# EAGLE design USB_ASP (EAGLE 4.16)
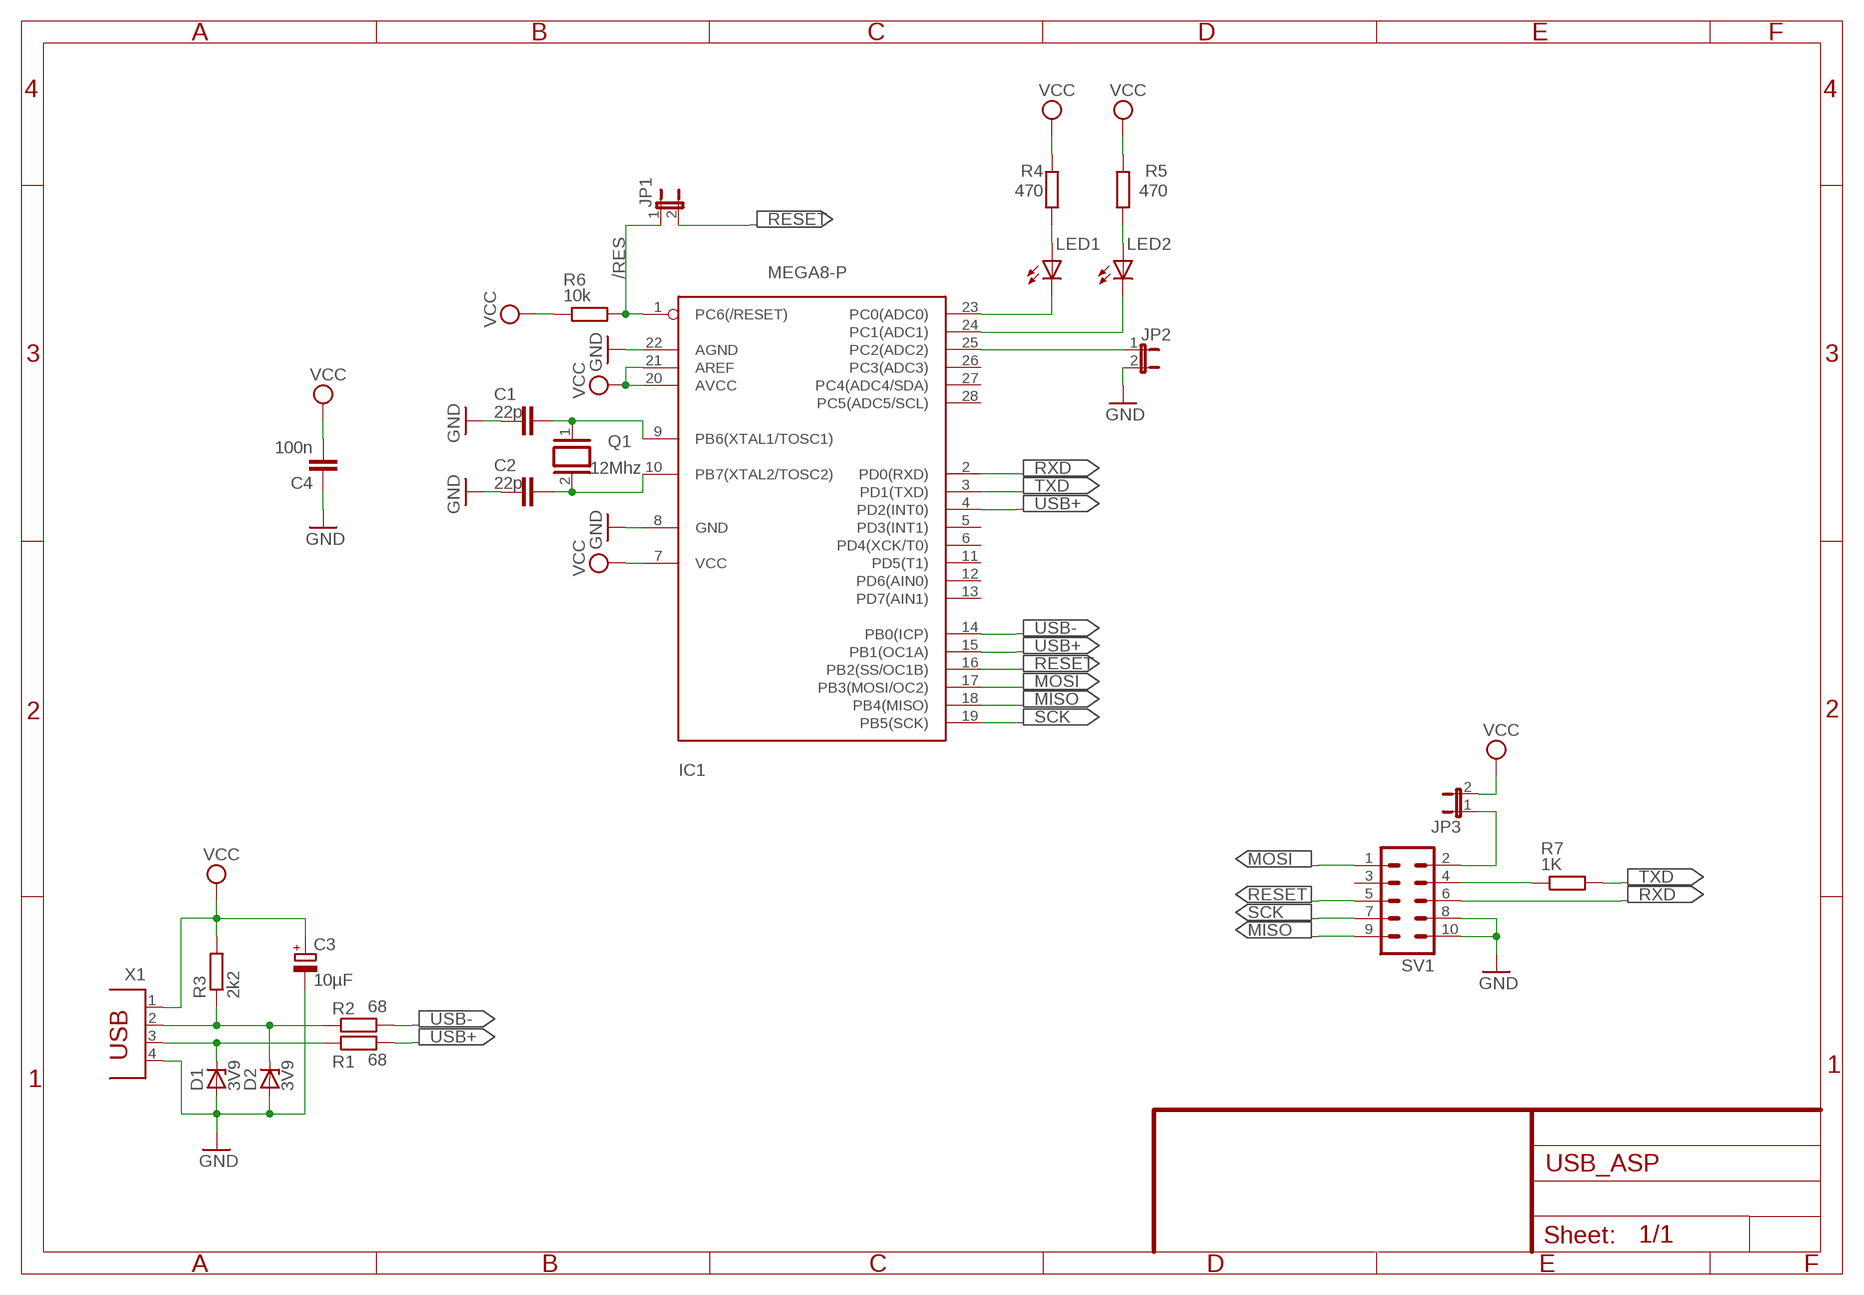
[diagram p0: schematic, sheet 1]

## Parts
C1  22p  C-EU025-024X044  [C025-024X044]
C2  22p  C-EU025-024X044  [C025-024X044]
C3  10µF  CPOL-EUE2.5-6  [E2,5-6]
C4  100n  C-EU025-024X044  [C025-024X044]
D1  3V9  BZX55  [DO35Z10]
D2  3V9  BZX55  [DO35Z10]
IC1  MEGA8-P  [DIL28-3]
JP1  JP1E  [JP1]
JP2  JP1E  [JP1]
JP3  JP1E  [JP1]
LED1  LED3MM  [LED3MM]
LED2  LED3MM  [LED3MM]
Q1  12Mhz  XTAL/S  [QS]
R1  68  R-EU_0207/10  [0207/10]
R2  68  R-EU_0207/10  [0207/10]
R3  2k2  R-EU_0207/10  [0207/10]
R4  470  R-EU_0207/10  [0207/10]
R5  470  R-EU_0207/10  [0207/10]
R6  10k  R-EU_0207/10  [0207/10]
R7  1K  R-EU_0207/10  [0207/10]
SV1  ML10L  [ML10L]
X1  PN61729  [PN61729]

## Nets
/RES: IC1.1(PC6(/RESET)) JP1.1 R6.2
GND: C1.1 C2.1 C3.- C4.1 D1.A D2.A IC1.8(GND) IC1.22(AGND) JP2.2 SV1.8 SV1.10 X1.4
MISO: IC1.18(PB4(MISO)) SV1.9
MOSI: IC1.17(PB3(MOSI/OC2)) SV1.1
N$3: C1.2 IC1.9(PB6(XTAL1/TOSC1)) Q1.1
N$4: C2.2 IC1.10(PB7(XTAL2/TOSC2)) Q1.2
N$5: D1.C R1.1 X1.3
N$6: D2.C R2.1 R3.1 X1.2
N$7: LED1.A R4.1
N$8: LED2.A R5.1
N$9: IC1.23(PC0(ADC0)) LED1.K(C)
N$10: IC1.24(PC1(ADC1)) LED2.K(C)
N$11: IC1.25(PC2(ADC2)) JP2.1
N$12: JP3.1 SV1.2
N$13: R7.1 SV1.4
RESET: IC1.16(PB2(SS/OC1B)) JP1.2 SV1.5
RXD: IC1.2(PD0(RXD)) SV1.6
SCK: IC1.19(PB5(SCK)) SV1.7
TXD: IC1.3(PD1(TXD)) R7.2
USB+: IC1.4(PD2(INT0)) IC1.15(PB1(OC1A)) R1.2
USB-: IC1.14(PB0(ICP)) R2.2
VCC: C3.+ C4.2 IC1.7(VCC) IC1.20(AVCC) IC1.21(AREF) JP3.2 R3.2 R4.2 R5.2 R6.1 X1.1
Unconnected: IC1.5(PD3(INT1)) IC1.6(PD4(XCK/T0)) IC1.11(PD5(T1)) IC1.12(PD6(AIN0)) IC1.13(PD7(AIN1)) IC1.26(PC3(ADC3)) IC1.27(PC4(ADC4/SDA)) IC1.28(PC5(ADC5/SCL)) SV1.3

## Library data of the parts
C1 C2 C4 = rcl:C-EU: CAPACITOR, European symbol
C3 = rcl:CPOL-EU: POLARIZED CAPACITOR, European symbol
D1 D2 = diode:BZX55: Z DIODE
IC1 = avr-1:MEGA8-P: MICROCONTROLLER 8 Kbytes FLASH 1 kbytes SRAM 512 bytes EEPROM USART 4-channel 10 bit ADC 2-channel 8 bit ADC
JP1-JP3 = jumper:JP1E: JUMPER
LED1 LED2 = led:LED: LED
Q1 = special:XTAL/S: CRYSTAL
R1-R7 = rcl:R-EU_: RESISTOR, European symbol
SV1 = con-harting-ml:ML10: HARTING
X1 = con-berg:PN61729: BERG USB connector

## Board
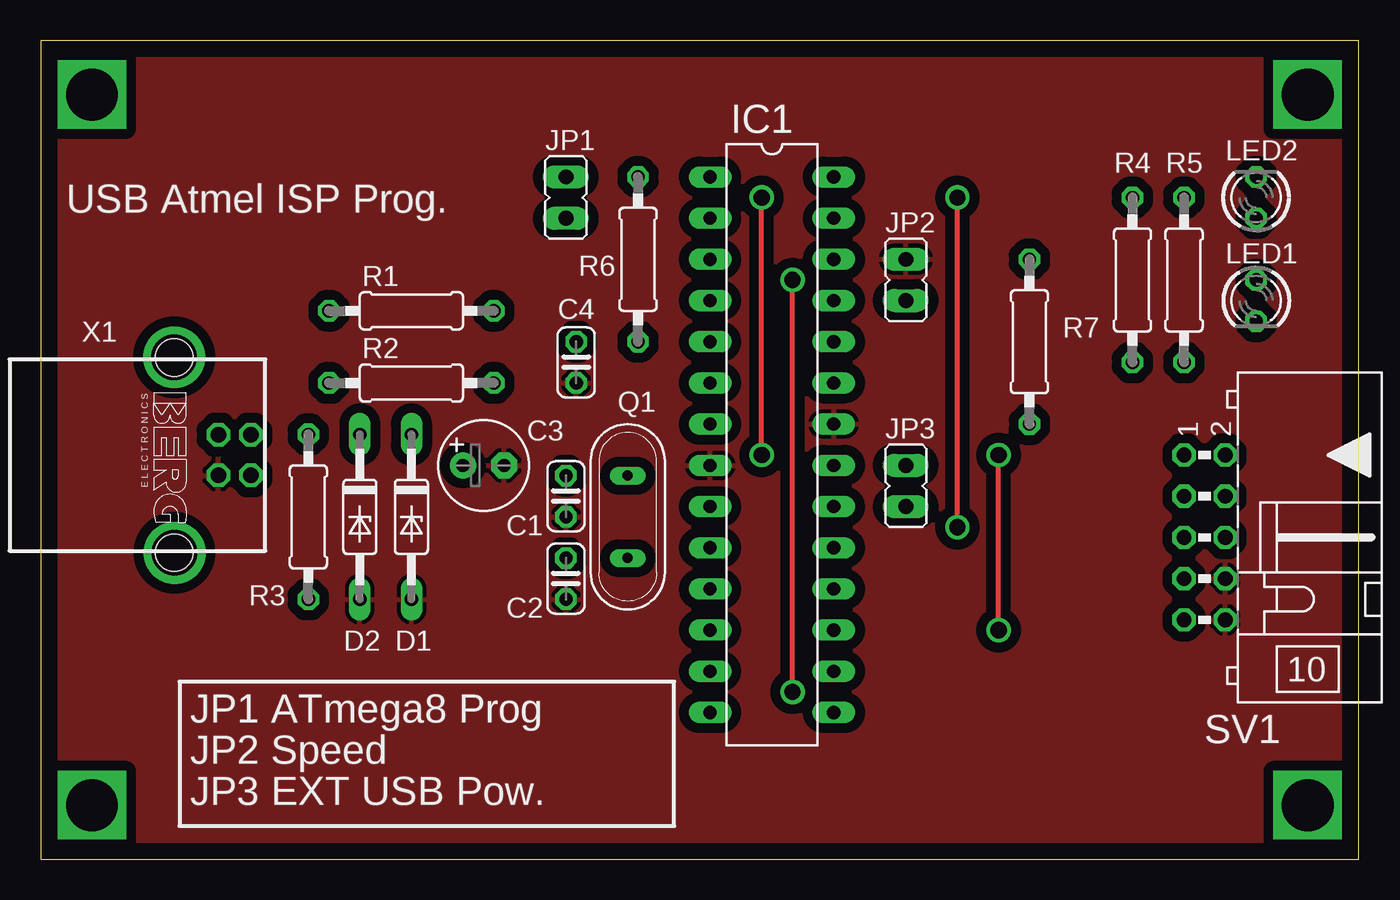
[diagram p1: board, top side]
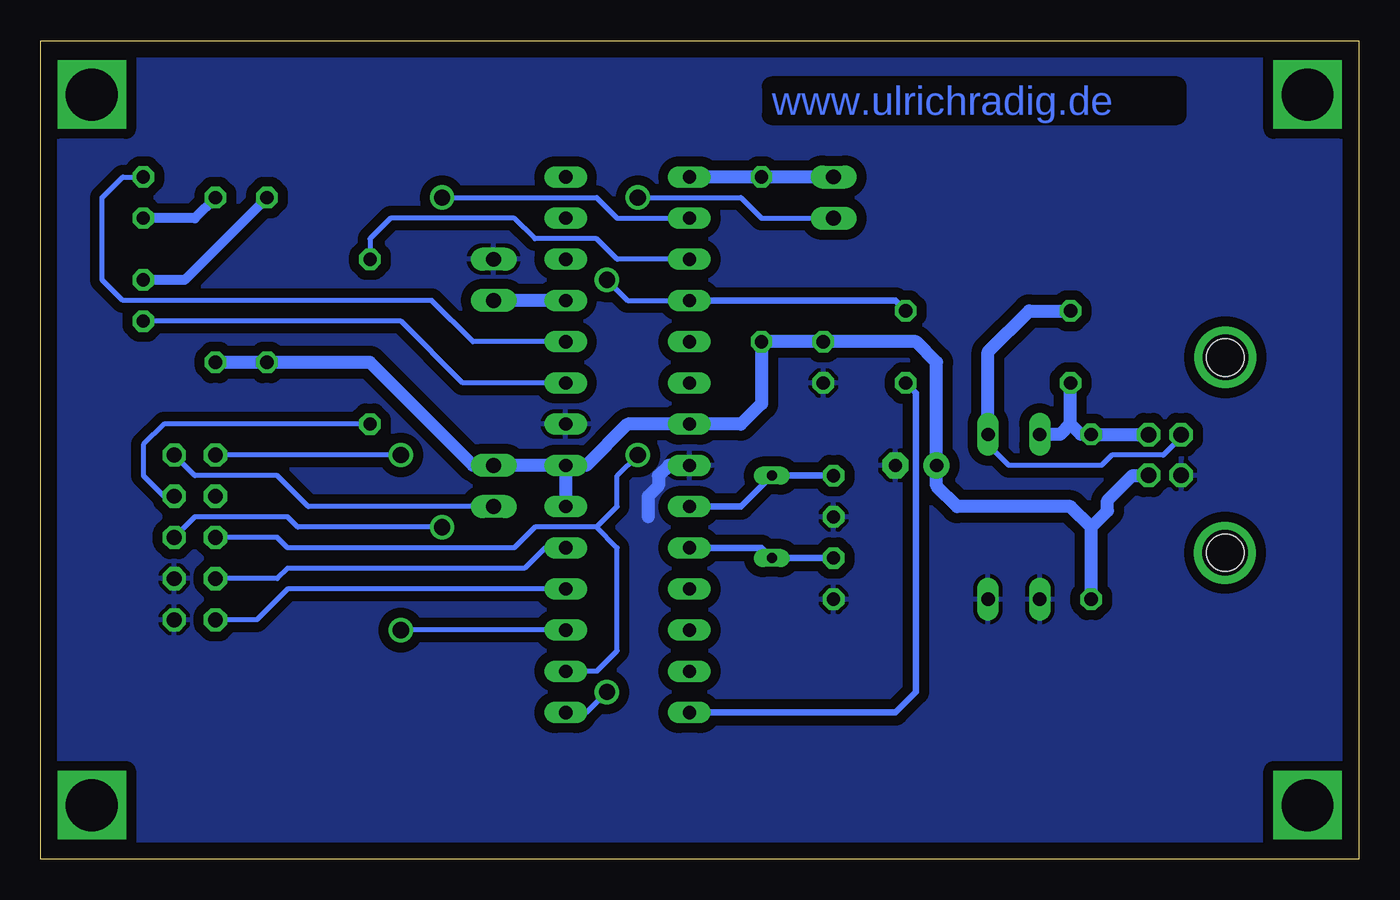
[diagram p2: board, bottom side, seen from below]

Size 81.26 x 50.47 mm. Coordinates in mm from the lower left corner, seen from the top.
Outline: 0,0 81.26,0 81.26,50.47 0,50.47 0,0
Copper layers (1*16): Top 0.035mm / dielectric 1.5mm / Bottom 0.035mm
Design rules "default": minimum track width 10mil, minimum drill 24mil, track to track 8mil, track to pad 8mil, pad to pad 8mil, via to via 8mil, smd to smd 8mil, copper to edge 40mil, drill to drill 8mil, minimum pad ring 10mil, minimum via ring 8mil, stop-mask expansion 4mil, vias tented up to drill 0mil, thermal gap 10mil

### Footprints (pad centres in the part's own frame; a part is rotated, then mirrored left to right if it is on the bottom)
C025-024X044 = drill 0.813 octagon: 1 -1.27,0; 2 1.27,0
E2,5-6 = drill 0.813 pad 1.6 round: + -1.27,0 | drill 0.813 pad 1.6 octagon: - 1.27,0
DO35Z10 = drill 0.813 long: A 5.08,0; C -5.08,0
DIL28-3 = drill 0.813 long: 1 -16.51,-3.81; 2 -13.97,-3.81; 3 -11.43,-3.81; 4 -8.89,-3.81; 5 -6.35,-3.81; 6 -3.81,-3.81; 7 -1.27,-3.81; 8 1.27,-3.81; 9 3.81,-3.81; 10 6.35,-3.81; 11 8.89,-3.81; 12 11.43,-3.81; 13 13.97,-3.81; 14 16.51,-3.81; 15 16.51,3.81; 16 13.97,3.81; 17 11.43,3.81; 18 8.89,3.81; 19 6.35,3.81; 20 3.81,3.81; 21 1.27,3.81; 22 -1.27,3.81; 23 -3.81,3.81; 24 -6.35,3.81; 25 -8.89,3.81; 26 -11.43,3.81; 27 -13.97,3.81; 28 -16.51,3.81
JP1 = drill 0.914 long: 1 0,-1.27; 2 0,1.27
LED3MM = drill 0.813 octagon: A -1.27,0; K 1.27,0
QS = drill 0.61 long: 1 -2.54,0; 2 2.54,0
0207/10 = drill 0.813 octagon: 1 -5.08,0; 2 5.08,0
ML10L = drill 0.914 octagon: 1 -5.08,-1.27; 2 -5.08,1.27; 3 -2.54,-1.27; 4 -2.54,1.27; 5 0,-1.27; 6 0,1.27; 7 2.54,-1.27; 8 2.54,1.27; 9 5.08,-1.27; 10 5.08,1.27
PN61729 = drill 0.95 octagon: 1 1.25,4.71; 2 -1.25,4.71; 3 -1.25,2.71; 4 1.25,2.71 | hole 2.3: -6.02,0; 6.02,0

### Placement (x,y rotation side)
C1  32.38,22.38 90 top
C2  32.38,17.3 90 top
C3  27.3,24.28 0 top
C4  33.02,30.63 90 top
D1  22.86,21.11 270 top
D2  19.68,21.11 270 top
IC1  45.08,25.55 270 top
JP1  32.38,40.79 180 top
JP2  53.34,35.71 0 top
JP3  53.34,23.01 0 top
LED1  74.93,34.44 270 top
LED2  74.93,40.79 90 top
Q1  36.19,21.11 270 top
R1  22.86,33.81 0 top
R2  22.86,29.36 0 top
R3  16.51,21.11 270 top
R4  67.31,35.71 270 top
R5  70.48,35.71 270 top
R6  36.82,36.98 90 top
R7  60.95,31.9 90 top
SV1  71.75,19.84 270 top
X1  8.25,24.92 270 top

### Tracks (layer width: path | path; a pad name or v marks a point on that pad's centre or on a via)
/RES
  Bottom 0.813: IC1.1 R6.2 JP1.1
GND
  Bottom 0.813: IC1.8 42.54,24.28 43.17,23.65 43.17,23.01 43.81,22.38 43.81,21.11
  pour Bottom (isolate 0.61): -0.01,50.32 81.28,50.32 81.28,0.15 -0.01,0.15
  pour Top (isolate 0.61): -0.01,50.32 -0.01,0.15 81.28,0.15 81.28,50.32
MISO
  Bottom 0.305: SV1.9 67.94,14.76 66.04,16.66 IC1.18
MOSI  (via drill 1)
  Top 0.305: v59.05,14.12 v59.05,24.92
  Bottom 0.305: IC1.17 v59.05,14.12 | v59.05,24.92 SV1.1
N$1  (via drill 2.8)
  other vias: 8.23,30.94
N$2  (via drill 2.8)
  other vias: 8.25,18.89
N$3
  Bottom 0.406: IC1.9 38.09,21.74 Q1.1 C1.2
N$4
  Bottom 0.406: IC1.10 36.82,19.2 Q1.2 C2.2
N$5
  Bottom 0.305: X1.3 10.96,26.02 12.06,24.92 15.23,24.92 15.87,24.28 21.59,24.28 22.86,25.55 D1.C
  Bottom 0.813: D1.C 22.86,31.27 20.32,33.81 R1.1
N$6
  Bottom 0.305: 16.48,26.17 R3.1
  Bottom 0.813: X1.2 16.48,26.17 | 17.78,26.82 R2.1 | R3.1 17.14,26.19 17.78,26.82 | 17.78,26.82 18.41,26.19 D2.C
N$7
  Bottom 0.61: LED1.A 72.39,35.71 R4.1
N$8
  Bottom 0.61: LED2.A 71.75,39.52 R5.1
N$9
  Bottom 0.305: LED1.K 59.05,33.17 55.24,29.36 IC1.23
N$10
  Bottom 0.305: IC1.24 54.6,31.9 57.14,34.44 76.2,34.44 77.47,35.71 77.47,40.79 76.2,42.06 LED2.K
N$11
  Bottom 0.813: IC1.25 JP2.1
N$12
  Bottom 0.305: JP3.1 64.77,21.74 66.67,23.65 71.75,23.65 SV1.2
N$13
  Bottom 0.305: SV1.4 73.66,22.38 74.93,23.65 74.93,25.55 73.66,26.82 R7.1
N$14  (via drill 3.2)
  other vias: 3.17,47.14
N$15  (via drill 3.2)
  other vias: 3.17,3.33
N$16  (via drill 3.2)
  other vias: 78.1,3.33
N$17  (via drill 3.2)
  other vias: 78.1,47.14
RESET  (via drill 1)
  Top 0.305: v44.45,24.92 v44.45,40.79
  Bottom 0.305: IC1.16 46.98,11.58 45.71,12.85 45.71,19.2 46.98,20.47 | 46.98,20.47 50.79,20.47 52.06,19.2 66.04,19.2 66.67,19.84 SV1.5 | JP1.2 36.82,39.52 38.09,40.79 v44.45,40.79 | 46.98,20.47 45.71,21.74 45.71,23.65 v44.45,24.92
RXD  (via drill 1)
  Top 0.305: v56.51,20.47 v56.51,40.79
  Bottom 0.305: SV1.6 71.75,21.11 66.04,21.11 65.4,20.47 v56.51,20.47 | v56.51,40.79 46.98,40.79 45.71,39.52 IC1.2
SCK
  Bottom 0.305: IC1.19 50.16,19.2 51.43,17.93 66.04,17.93 66.67,17.3 SV1.7
TXD
  Bottom 0.305: IC1.3 45.71,36.98 46.98,38.25 50.79,38.25 52.06,39.52 59.68,39.52 60.95,38.25 R7.2
USB+  (via drill 1)
  Top 0.305: v46.35,10.31 v46.35,35.71
  Bottom 0.305: v46.35,35.71 45.08,34.44 IC1.4 | v46.35,10.31 47.62,9.04 IC1.15
  Bottom 0.406: IC1.4 28.57,34.44 R1.2
USB-
  Bottom 0.406: R2.2 27.3,28.73 27.3,10.31 28.57,9.04 IC1.14
VCC
  Bottom 0.813: X1.1 13.96,23.65 15.5,22.11 15.5,21.48 16.51,20.47 | R3.2 16.51,20.47 | 16.51,20.47 17.78,21.74 24.76,21.74 26.03,23.01 C3.+ 26.03,30.63 27.3,31.9 C4.2 R6.1 36.82,28.09 38.09,26.82 IC1.7 45.08,26.82 47.62,24.28 IC1.21 | IC1.21 IC1.20 | R5.2 R4.2 60.95,30.63 54.6,24.28 JP3.2 IC1.21

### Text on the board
Bottom: www.ulrichradig.de
tPlace: USB Atmel ISP Prog. | JP1 ATmega8 Prog | JP2 Speed | JP3 EXT USB Pow.
bStop: www.ulrichradig.de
